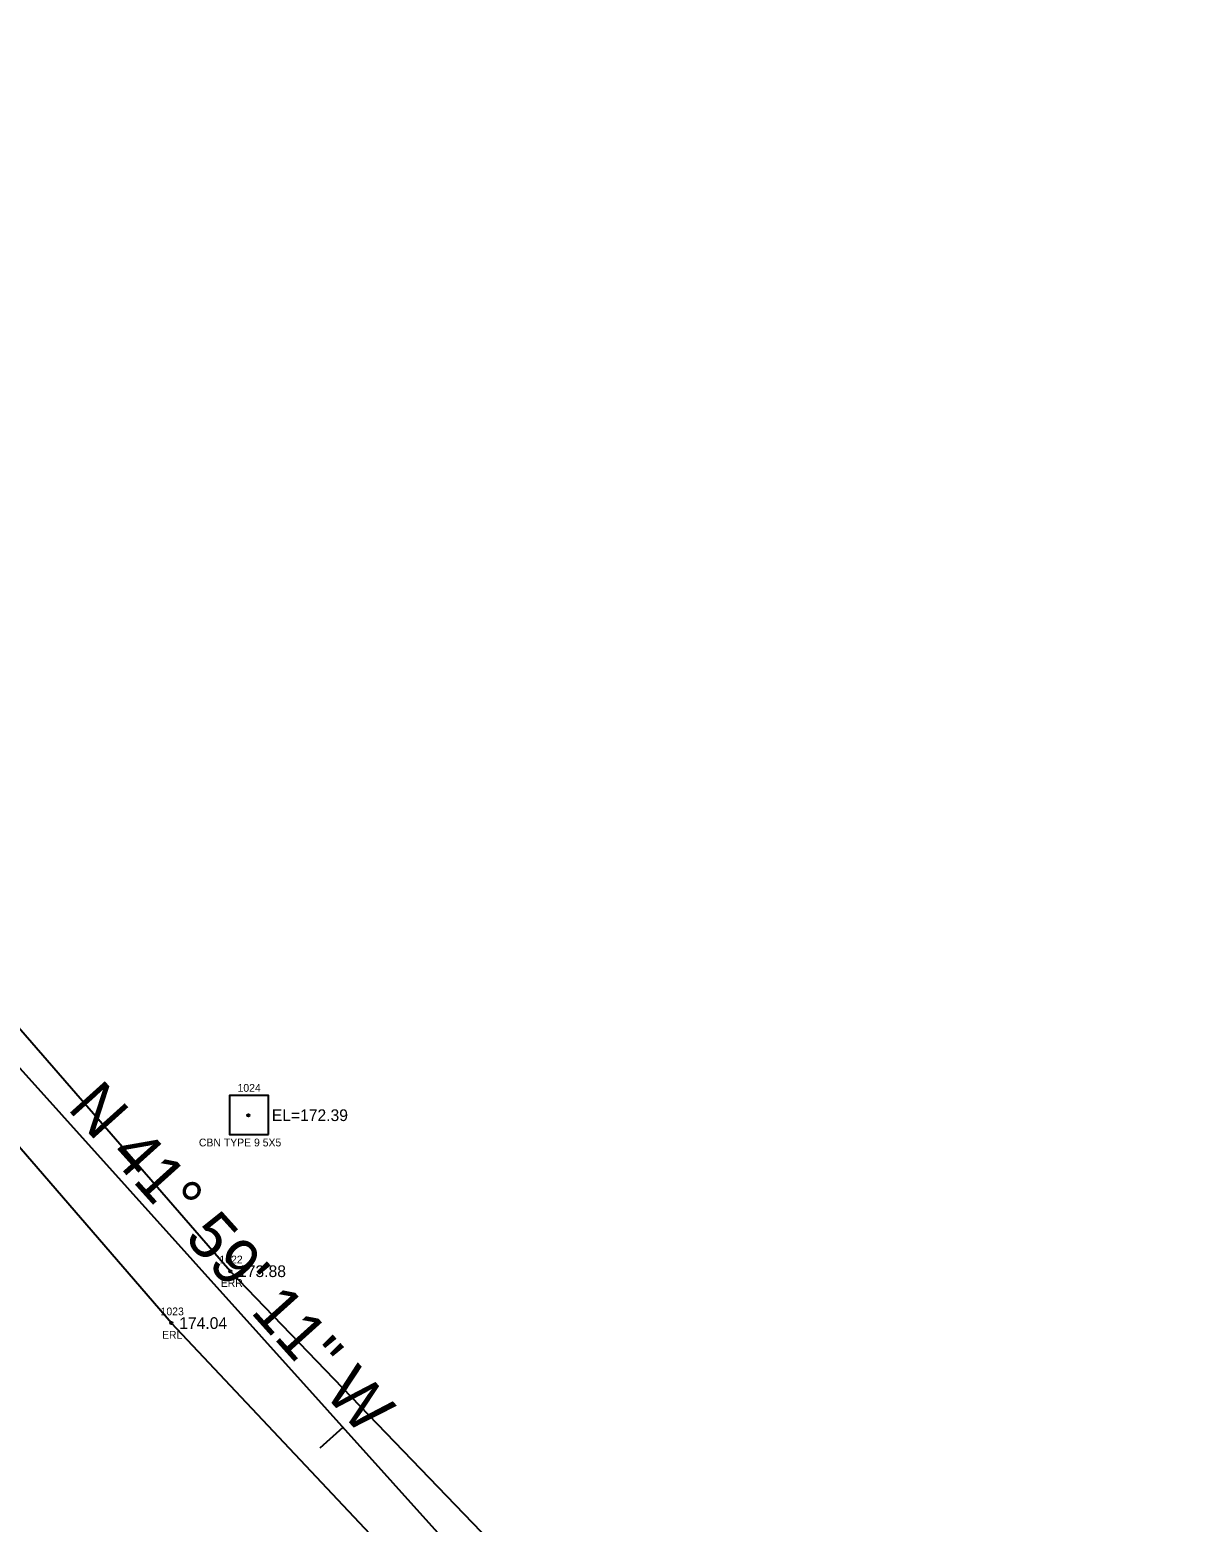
# Model space of a CAD drawing. Extents: x 1970735 to 1971583, y 794736 to 795766.
# Drawn here: x 1970992.3 to 1971142.5, y 795256 to 795447.2 of the extents above; entities that cross this region are included whole.
import ezdxf

# ---------------------------------------------------------------- set-up
doc = ezdxf.new("R2010")
doc.units = 0
for name, color, linetype in [('RD_EX_DR_Inlet', 7, 'Continuous'), ('RD_EX_DR_Inlet_txCode', 7, 'Continuous'), ('RD_EX_Road', 7, 'Continuous'), ('RD_EX_Road_txCode', 7, 'Continuous'), ('RD_EX_TX_DR_Inlet_ELEV', 7, 'Continuous'), ('RD_EX_TX_Road_ELEV', 7, 'Continuous'), ('RD_HC_Cl', 7, 'Continuous'), ('RD_HC_Data', 7, 'Continuous'), ('RD_HC_Data_Tic', 7, 'Continuous'), ('RD_SMD_Locator', 7, 'Continuous')]:
    doc.layers.add(name, color=color, linetype=linetype)

msp = doc.modelspace()

# ---------------------------------------------------------------- linework, layer by layer
at = {"layer": 'RD_EX_DR_Inlet'}
msp.add_line((1971022.87, 795305.67), (1971022.87, 795310.67), dxfattribs=at)
msp.add_lwpolyline([(1971022.87, 795305.67), (1971022.87, 795310.67), (1971017.87, 795310.67), (1971017.87, 795305.67)], close=True, dxfattribs=at)
at = {"layer": 'RD_EX_Road'}
for points in [[(1971550.5, 794861.13), (1971472.2, 794904.32), (1971401.49, 794943.08), (1971346.58, 794975.73), (1971286.05, 795024.56), (1971217.92, 795079.41), (1971172.76, 795121.06), (1971082.31, 795221.27), (1971017.96, 795288.13), (1970931.75, 795387.33), (1970878.11, 795452.95), (1970856.35, 795489.48), (1970840.29, 795529.45), (1970827.57, 795574.31), (1970814.81, 795635.62), (1970805.04, 795696.13), (1970791.39, 795763.83)], [(1971543.68, 794851.6), (1971507.7, 794872.08), (1971504.76, 794847.96), (1971494.98, 794846.56), (1971488.18, 794883), (1971469.72, 794893.79), (1971395.92, 794934.76), (1971339.47, 794967.38), (1971278.34, 795016.59), (1971212.1, 795072.1), (1971165.04, 795113.96), (1971074.42, 795213.48), (1971010.42, 795281.48), (1970922.49, 795383.19), (1970882.25, 795365.41), (1970854.66, 795404.07), (1970871.45, 795443.76), (1970844.39, 795483.83), (1970828.93, 795526.65), (1970817.76, 795568.61), (1970806.82, 795600.57), (1970787.72, 795602.49), (1970770.58, 795591.56)]]:
    msp.add_lwpolyline(points, dxfattribs=at)
at = {"layer": 'RD_HC_Cl'}
msp.add_line((1971124.57, 795165.7), (1970901.81, 795413.21), dxfattribs=at)
at = {"layer": 'RD_HC_Data_Tic'}
msp.add_line((1971032.4, 795268.12), (1971029.42, 795265.44), dxfattribs=at)
at = {"layer": 'RD_SMD_Locator'}
for centre in [(1971020.28, 795308.13), (1971017.96, 795288.13), (1971010.42, 795281.48)]:
    msp.add_circle(centre, 0.15, dxfattribs=at)

# ---------------------------------------------------------------- texts
at = {"layer": 'RD_EX_DR_Inlet_txCode'}
for s, p in [('1024', (1971018.89, 795311.13)), ('CBN TYPE 9 5X5', (1971013.94, 795304.13))]:
    msp.add_text(s, height=1, dxfattribs=at).set_placement(p)
at = {"layer": 'RD_EX_Road_txCode'}
for s, p in [('1022', (1971016.57, 795289.13)), ('ERR', (1971016.73, 795286.13)), ('1023', (1971009.03, 795282.48)), ('ERL', (1971009.21, 795279.48))]:
    msp.add_text(s, height=1, dxfattribs=at).set_placement(p)
at = {"layer": 'RD_EX_TX_DR_Inlet_ELEV'}
msp.add_text('EL=172.39', height=1.5, dxfattribs=at).set_placement((1971023.28, 795307.38))
at = {"layer": 'RD_EX_TX_Road_ELEV'}
for s, p in [('173.88', (1971018.96, 795287.38)), ('174.04', (1971011.42, 795280.73))]:
    msp.add_text(s, height=1.5, dxfattribs=at).set_placement(p)
at = {"layer": 'RD_HC_Data'}
msp.add_text('N 41%%d 59\' 11" W', height=6, rotation=311.9864, dxfattribs=at).set_placement((1970996.98, 795308.96))

doc.saveas('drawing.dxf')
